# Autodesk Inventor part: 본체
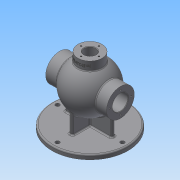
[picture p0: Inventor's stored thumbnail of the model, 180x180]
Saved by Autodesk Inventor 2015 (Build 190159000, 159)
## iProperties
Created: 2020-08
Part Number: 본체
Material: 일반
Document SubType Name: Modeling
Designer: user
Density: 1 g/cm^3
Appearance: 기본값
Author: user
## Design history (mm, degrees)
node "작업 평면4"
sketch "스케치7"
  geometry: C1 r 85 at (0, 0); 1 further point
  constraints: 1 centre point, 1 coincident
  dimensions: "d15" = 170 diameter of C1
sketch "스케치1"
  geometry: L1 (95.587, 0)-(-77.665, 0); A1 r 53 centre (0, 0) between (-53, 0) and (53, 0); A2 r 43 centre (0, 0) between (-43, 0) and (43, 0); 1 further point
  constraints: 4 point on circle, 4 point on line, 2 centre point, 2 coincident, 2 end point, 1 horizontal
  dimensions: "d0" = 106 diameter of A1
revolve "회전1" sketch "스케치1" stored, may be unused: angle "d3" = 90 deg
node "작업 평면2"
sketch "스케치3"
  geometry: C1 r 31 at (0, 0); 1 further point
  constraints: 1 centre point, 1 coincident
  dimensions: "d6" = 62 diameter of C1
extrude "돌출1" join sketch "스케치3" distance "d7" = 136; taper "d8" = 0 deg
extrude "돌출3" join sketch "스케치7" distance "d16" = 10; taper "d17" = 0 deg
sketch "스케치8"
  geometry: C1 r 85 at (0, 0) reference; A1 r 72.5 centre (0, 0) between (-72.5, 0) and (0, 72.5); 2 further points
  constraints: 4 point on circle, 1 centre point, 1 coincident
  dimensions: "d18" = 145 diameter of A1
hole "구멍1" sketch "스케치8" at (-72.5, 0), (0, 72.5), (72.5, 0), (0, -72.5) diameter "d19" = 9; stored, may be unused: countersink angle "d23" = 90 deg, drill point angle "d25" = 118 deg; dims "d20" = 6, "d21" = 4, "d22" = 2, "d24" = 9
fillet "모깎기1" dims "d26" = 3
node "작업 평면5"
sketch "스케치9"
  geometry: C1 r 27 at (0, 0); 1 further point
  constraints: 1 centre point, 1 coincident
  dimensions: "d28" = 54 diameter of C1
extrude "돌출4" join sketch "스케치9" distance "d29" = 65; taper "d30" = 0 deg
sketch "스케치10"
  geometry: L1 (0, 0)-(52, 0); L2 (52, 0)-(52, -85); L3 (52, -85)-(0, -85); L4 (0, -85)-(0, 0); L5 (0, 0)-(-52, 0); L6 (-52, 0)-(-52, -85); L7 (-52, -85)-(0, -85); L8 (0, -85)-(0, 0)
  constraints: 16 end point, 4 parallel, 2 horizontal, 2 perpendicular
  dimensions: "d31" = 52 distance of L2.end L3.end; "d32" = 85 distance of L1.end L2.end; "d33" = 52 distance of L7.end L6.end; "d34" = 85 distance of L6.end L5.end
extrude "돌출5" join sketch "스케치10" stored distance "d35" = 8; taper "d36" = 0 deg
sketch "스케치11"
  geometry: L1 (0, 0)-(-85, 0); L2 (-85, 0)-(-85, -43); L3 (-85, -43)-(0, -43); L4 (0, -43)-(0, 0); L5 (0, 0)-(-85, 0); L6 (-85, 0)-(-85, 43); L7 (-85, 43)-(0, 43); L8 (0, 43)-(0, 0)
  constraints: 16 end point, 4 parallel, 2 horizontal, 2 perpendicular
  dimensions: "d37" = 85 distance of L3.end L2.end; "d38" = 43 distance of L2.end L1.end; "d39" = 85 distance of L6.end L7.end; "d40" = 43 distance of L5.end L6.end
extrude "돌출6" join sketch "스케치11" stored distance "d41" = 8; taper "d42" = 0 deg
sketch "스케치12"
  geometry: C1 r 27 at (0, 0) reference; C2 r 13 at (0, 0)
  constraints: 1 centre point, 1 coincident
  dimensions: "d43" = 26 diameter of C2
extrude "돌출7" cut sketch "스케치12" distance "d44" = 65; taper "d45" = 0 deg
sketch "스케치13"
  geometry: C1 r 31 at (0, 0) reference; C2 r 17.5 at (0, 0)
  constraints: 1 centre point, 1 coincident
  dimensions: "d46" = 35 diameter of C2
extrude "돌출8" cut sketch "스케치13" stored distance "d47" = 65; taper "d48" = 0 deg
sketch "스케치14"
  geometry: L1 (0, 99.007)-(0, -122.152); A1 r 43 centre (0, 0) between (0, -43) and (0, 43); 1 further point
  constraints: 2 end point, 2 point on circle, 2 point on line, 1 centre point, 1 coincident, 1 vertical
  dimensions: "d49" = 86 diameter of A1
revolve "회전2" sketch "스케치14" stored, may be unused: angle "d50" = 90 deg
sketch "스케치15"
  geometry: C1 r 27 at (0, 0) reference; A1 r 20 centre (0, 0) between (-20, 0) and (0, -20); 2 further points
  constraints: 4 point on circle, 1 centre point, 1 coincident
  dimensions: "d51" = 40 diameter of A1
hole "구멍2" sketch "스케치15" at (-20, 0), (0, -20), (20, 0), (0, 20) diameter "d52" = 3.242; stored, may be unused: countersink angle "d56" = 90 deg, drill point angle "d58" = 118 deg; dims "d53" = 12, "d54" = 4, "d55" = 2, "d57" = 15
sketch "스케치16"
  geometry: C1 r 31 at (0, 0) reference; A1 r 24 centre (0, 0) between (0, 24) and (-24, 0); 2 further points
  constraints: 4 point on circle, 1 centre point, 1 coincident
  dimensions: "d59" = 48 diameter of A1
sketch "스케치17"
  geometry: C1 r 31 at (0, 0) reference; A1 r 24 centre (0, 0) between (0, 24) and (-24, 0); 2 further points
  constraints: 4 point on circle, 1 centre point, 1 coincident
  dimensions: "d60" = 48 diameter of A1
hole "구멍3" sketch "스케치17" at (0, 24), (24, 0), (0, -24), (-24, 0) diameter "d61" = 3.242; stored, may be unused: countersink angle "d65" = 90 deg, drill point angle "d67" = 118 deg; dims "d62" = 12, "d63" = 4, "d64" = 2, "d66" = 15
hole "구멍4" sketch "스케치16" diameter "d68" = 3.242; stored, may be unused: countersink angle "d72" = 90 deg, drill point angle "d74" = 118 deg; dims "d69" = 12, "d70" = 4, "d71" = 2, "d73" = 15
fillet "모깎기2" dims "d75" = 3
chamfer "모따기1" distance "d76" = 1; stored, may be unused: second distance "d77" = 2, angle "d78" = 45 deg
fillet "모깎기3" dims "d79" = 3
fillet "모깎기4" dims "d80" = 3
node "작업 평면6"
sketch "스케치18"
  geometry: L1 (0, 0)-(0, 56); L2 (-40.249, 68.099)-(41.063, 68.099); L3 (41.063, 68.099)-(41.063, 42.486); L4 (41.063, 42.486)-(-40.249, 42.486); L5 (-40.249, 42.486)-(-40.249, 68.099)
  constraints: 2 end point, 1 vertical, 2 other
  dimensions: "d82" = 56 distance of L1.start L1.end
feature "엠보싱1" sketch "스케치18" dims "d0" = 106, "d18" = 145, "d83" = 0.5, "d84" = 0
node "작업 평면7"
sketch "스케치19"
  geometry: C1 r 18.5 at (0, 0); 1 further point
  constraints: 1 centre point, 1 coincident
  dimensions: "d86" = 37 diameter of C1
extrude "돌출9" cut sketch "스케치19" distance "d87" = 1.75; taper "d88" = 0 deg
node "솔리드1"
other parameters: "d5" = 68, "d14" = -85, "d27" = 65, "d81" = 76.5, "d85" = -16
